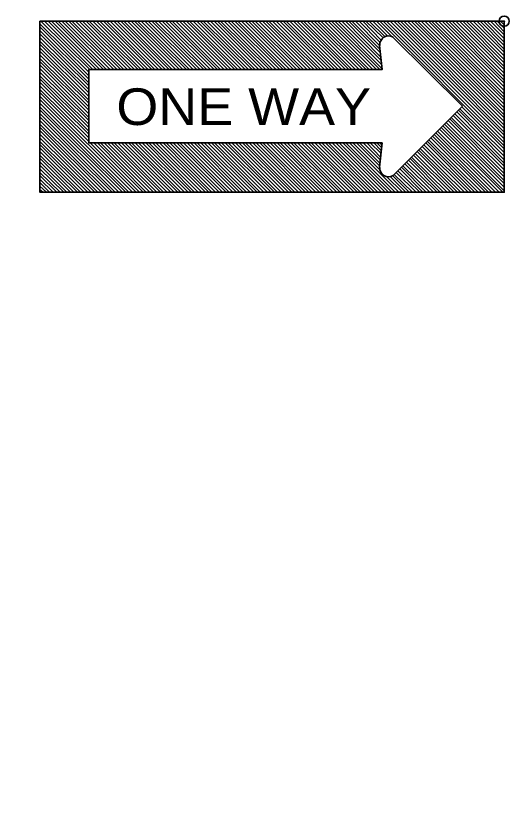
# Model space of a CAD drawing. Extents: x -198 to 658, y -402 to 142.
# Drawn here: x 499.68 to 522.95, y -202.97 to -165.99 of the extents above; entities that cross this region are included whole.
import ezdxf
from ezdxf.enums import TextEntityAlignment as Align

# ---------------------------------------------------------------- set-up
doc = ezdxf.new("R2010")
doc.units = 0
doc.header["$LTSCALE"] = 0.96
doc.header["$PDMODE"] = 32
doc.header["$PDSIZE"] = 0.48
doc.layers.add('1', color=7, linetype='Continuous', lineweight=35)

msp = doc.modelspace()

# ---------------------------------------------------------------- linework, layer by layer
at = {"layer": '1'}
for p, q in [((503.1263, -168.6473), (500.8223, -166.3673)), ((503.1743, -168.5273), (500.8703, -166.2473)), ((503.3183, -168.5273), (501.0383, -166.2473)), ((503.4863, -168.5273), (501.2063, -166.2473)), ((503.6543, -168.5273), (501.3743, -166.2473)), ((503.8223, -168.5273), (501.5423, -166.2473)), ((503.9663, -168.5273), (501.6863, -166.2473)), ((504.1343, -168.5273), (501.8543, -166.2473)), ((504.3023, -168.5273), (502.0223, -166.2473)), ((504.4703, -168.5273), (502.1903, -166.2473)), ((504.6383, -168.5273), (502.3343, -166.2473)), ((504.7823, -168.5273), (502.5023, -166.2473)), ((504.9503, -168.5273), (502.6703, -166.2473)), ((505.1183, -168.5273), (502.8383, -166.2473)), ((505.2863, -168.5273), (503.0063, -166.2473)), ((505.4543, -168.5273), (503.1503, -166.2473)), ((505.5983, -168.5273), (503.3183, -166.2473)), ((505.7663, -168.5273), (503.4863, -166.2473)), ((505.9343, -168.5273), (503.6543, -166.2473)), ((506.1023, -168.5273), (503.8223, -166.2473)), ((506.2463, -168.5273), (503.9663, -166.2473)), ((506.4143, -168.5273), (504.1343, -166.2473)), ((506.5823, -168.5273), (504.3023, -166.2473)), ((506.7503, -168.5273), (504.4703, -166.2473)), ((506.9183, -168.5273), (504.6383, -166.2473)), ((507.0623, -168.5273), (504.7823, -166.2473)), ((507.2303, -168.5273), (504.9503, -166.2473)), ((507.3983, -168.5273), (505.1183, -166.2473)), ((507.5663, -168.5273), (505.2863, -166.2473)), ((507.7343, -168.5273), (505.4303, -166.2473)), ((507.8783, -168.5273), (505.5983, -166.2473)), ((508.0463, -168.5273), (505.7663, -166.2473)), ((508.2143, -168.5273), (505.9343, -166.2473)), ((508.3823, -168.5273), (506.1023, -166.2473)), ((508.5503, -168.5273), (506.2463, -166.2473)), ((508.6943, -168.5273), (506.4143, -166.2473)), ((508.8623, -168.5273), (506.5823, -166.2473)), ((509.0303, -168.5273), (506.7503, -166.2473)), ((509.1983, -168.5273), (506.9183, -166.2473)), ((509.3423, -168.5273), (507.0623, -166.2473)), ((509.5103, -168.5273), (507.2303, -166.2473)), ((509.6783, -168.5273), (507.3983, -166.2473)), ((509.8463, -168.5273), (507.5663, -166.2473)), ((510.0143, -168.5273), (507.7343, -166.2473)), ((510.1583, -168.5273), (507.8783, -166.2473)), ((510.3263, -168.5273), (508.0463, -166.2473)), ((510.4943, -168.5273), (508.2143, -166.2473)), ((510.6623, -168.5273), (508.3823, -166.2473)), ((510.8303, -168.5273), (508.5263, -166.2473)), ((510.9743, -168.5273), (508.6943, -166.2473)), ((511.1423, -168.5273), (508.8623, -166.2473)), ((511.3103, -168.5273), (509.0303, -166.2473)), ((511.4783, -168.5273), (509.1983, -166.2473)), ((511.6463, -168.5273), (509.3423, -166.2473)), ((511.7903, -168.5273), (509.5103, -166.2473)), ((511.9583, -168.5273), (509.6783, -166.2473)), ((512.1263, -168.5273), (509.8463, -166.2473)), ((512.2943, -168.5273), (510.0143, -166.2473)), ((512.4383, -168.5273), (510.1583, -166.2473)), ((512.6063, -168.5273), (510.3263, -166.2473)), ((512.7743, -168.5273), (510.4943, -166.2473)), ((512.9423, -168.5273), (510.6623, -166.2473)), ((513.1103, -168.5273), (510.8063, -166.2473)), ((513.2543, -168.5273), (510.9743, -166.2473)), ((513.4223, -168.5273), (511.1423, -166.2473)), ((513.5903, -168.5273), (511.3103, -166.2473)), ((513.7583, -168.5273), (511.4783, -166.2473)), ((513.9263, -168.5273), (511.6223, -166.2473)), ((514.0703, -168.5273), (511.7903, -166.2473)), ((514.2383, -168.5273), (511.9583, -166.2473)), ((514.4063, -168.5273), (512.1263, -166.2473)), ((514.5743, -168.5273), (512.2943, -166.2473)), ((514.7183, -168.5273), (512.4383, -166.2473)), ((514.8863, -168.5273), (512.6063, -166.2473)), ((515.0543, -168.5273), (512.7743, -166.2473)), ((515.2223, -168.5273), (512.9423, -166.2473)), ((515.3903, -168.5273), (513.1103, -166.2473)), ((515.5343, -168.5273), (513.2543, -166.2473)), ((515.7023, -168.5273), (513.4223, -166.2473)), ((515.8703, -168.5273), (513.5903, -166.2473)), ((516.0383, -168.5273), (513.7583, -166.2473)), ((516.2063, -168.5273), (513.9023, -166.2473)), ((516.3503, -168.5273), (514.0703, -166.2473)), ((516.5183, -168.5273), (514.2383, -166.2473)), ((516.6863, -168.5273), (514.4063, -166.2473)), ((516.8543, -168.5273), (514.5743, -166.2473)), ((516.9263, -168.4553), (514.7183, -166.2473)), ((516.9263, -168.2873), (514.8863, -166.2473)), ((516.9023, -168.0953), (515.0543, -166.2473)), ((516.8783, -167.9273), (515.2223, -166.2473)), ((516.8783, -167.7353), (515.3903, -166.2473)), ((516.8543, -167.5673), (515.5343, -166.2473)), ((516.8303, -167.3993), (515.7023, -166.2473)), ((516.8543, -167.2313), (515.8703, -166.2473)), ((516.9023, -167.1353), (516.0383, -166.2473)), ((516.9983, -167.0393), (516.1823, -166.2473)), ((517.0943, -166.9913), (516.3503, -166.2473)), ((517.2143, -166.9433), (516.5183, -166.2473)), ((517.4063, -166.9673), (516.6863, -166.2473)), ((522.7103, -172.1273), (516.8543, -166.2473)), ((522.7103, -171.9593), (516.9983, -166.2473)), ((522.7103, -171.7913), (517.1663, -166.2473)), ((522.7103, -171.6233), (517.3343, -166.2473)), ((522.7103, -171.4793), (517.5023, -166.2473)), ((522.7103, -171.3113), (517.6703, -166.2473)), ((522.7103, -171.1433), (517.8143, -166.2473)), ((522.7103, -170.9753), (517.9823, -166.2473)), ((522.7103, -170.8073), (518.1503, -166.2473)), ((522.7103, -170.6633), (518.3183, -166.2473)), ((522.7103, -170.4953), (518.4863, -166.2473)), ((522.7103, -170.3273), (518.6303, -166.2473)), ((522.7103, -170.1593), (518.7983, -166.2473)), ((522.7103, -169.9913), (518.9663, -166.2473)), ((522.7103, -169.8473), (519.1343, -166.2473)), ((522.7103, -169.6793), (519.2783, -166.2473)), ((522.7103, -169.5113), (519.4463, -166.2473)), ((522.7103, -169.3433), (519.6143, -166.2473)), ((522.7103, -169.1753), (519.7823, -166.2473)), ((522.7103, -169.0313), (519.9503, -166.2473)), ((522.7103, -168.8633), (520.0943, -166.2473)), ((522.7103, -168.6953), (520.2623, -166.2473)), ((522.7103, -168.5273), (520.4303, -166.2473)), ((522.7103, -168.3833), (520.5983, -166.2473)), ((522.7103, -168.2153), (520.7663, -166.2473)), ((522.7103, -168.0473), (520.9103, -166.2473)), ((522.7103, -167.8793), (521.0783, -166.2473)), ((522.7103, -167.7113), (521.2463, -166.2473)), ((522.7103, -167.5673), (521.4143, -166.2473)), ((522.7103, -167.3993), (521.5823, -166.2473)), ((522.7103, -167.2313), (521.7263, -166.2473)), ((522.7103, -167.0633), (521.8943, -166.2473)), ((522.7103, -166.8953), (522.0623, -166.2473)), ((522.7103, -166.7513), (522.2303, -166.2473)), ((522.7103, -166.5833), (522.3743, -166.2473)), ((522.7103, -166.4153), (522.5423, -166.2473)), ((503.1263, -168.8153), (500.8223, -166.5113)), ((503.1263, -168.9833), (500.8223, -166.6793)), ((503.1263, -169.1513), (500.8223, -166.8473)), ((503.1263, -169.2953), (500.8223, -167.0153)), ((520.7423, -170.2553), (517.4783, -167.0153)), ((503.1263, -169.4633), (500.8223, -167.1833)), ((503.1263, -169.6313), (500.8223, -167.3273)), ((503.1263, -169.7993), (500.8223, -167.4953)), ((503.1263, -169.9673), (500.8223, -167.6633)), ((503.1263, -170.1113), (500.8223, -167.8313)), ((503.1263, -170.2793), (500.8223, -167.9993)), ((503.1263, -170.4473), (500.8223, -168.1433)), ((503.1263, -170.6153), (500.8223, -168.3113)), ((503.1263, -170.7833), (500.8223, -168.4793)), ((503.1263, -170.9273), (500.8223, -168.6473)), ((503.1263, -171.0953), (500.8223, -168.8153)), ((503.1263, -171.2633), (500.8223, -168.9593)), ((503.1263, -171.4313), (500.8223, -169.1273)), ((503.1263, -171.5753), (500.8223, -169.2953)), ((503.1263, -171.7433), (500.8223, -169.4633)), ((503.1263, -171.9113), (500.8223, -169.6073)), ((505.3583, -174.3113), (500.8223, -169.7753)), ((505.1903, -174.3113), (500.8223, -169.9433)), ((505.0223, -174.3113), (500.8223, -170.1113)), ((504.8783, -174.3113), (500.8223, -170.2793)), ((504.7103, -174.3113), (500.8223, -170.4233)), ((517.4783, -173.5193), (520.7423, -170.2553)), ((522.7103, -172.6073), (520.5503, -170.4473)), ((522.7103, -172.4393), (520.6223, -170.3753)), ((522.7103, -172.2713), (520.7183, -170.2793)), ((504.5423, -174.3113), (500.8223, -170.5913)), ((504.3743, -174.3113), (500.8223, -170.7593)), ((522.7103, -173.4233), (520.1423, -170.8553)), ((522.7103, -173.2553), (520.2143, -170.7833)), ((522.7103, -173.0873), (520.3103, -170.6873)), ((522.7103, -172.9433), (520.3823, -170.6153)), ((522.7103, -172.7753), (520.4783, -170.5193)), ((504.2303, -174.3113), (500.8223, -170.9273)), ((504.0623, -174.3113), (500.8223, -171.0953)), ((503.8943, -174.3113), (500.8223, -171.2393)), ((522.7103, -174.0713), (519.8303, -171.1913)), ((522.7103, -173.9033), (519.9023, -171.0953)), ((522.7103, -173.7593), (519.9743, -171.0233)), ((522.7103, -173.5913), (520.0703, -170.9273)), ((503.7263, -174.3113), (500.8223, -171.4073)), ((503.5583, -174.3113), (500.8223, -171.5753)), ((522.1343, -174.3113), (519.4223, -171.5993)), ((522.3023, -174.3113), (519.4943, -171.5033)), ((522.4703, -174.3113), (519.5663, -171.4313)), ((522.6383, -174.3113), (519.6623, -171.3353)), ((522.7103, -174.2393), (519.7343, -171.2633)), ((503.4143, -174.3113), (500.8223, -171.7433)), ((503.2463, -174.3113), (500.8223, -171.9113)), ((505.5263, -174.3113), (503.1983, -171.9833)), ((505.6943, -174.3113), (503.3663, -171.9833)), ((505.8383, -174.3113), (503.5343, -171.9833)), ((506.0063, -174.3113), (503.6783, -171.9833)), ((506.1743, -174.3113), (503.8463, -171.9833)), ((506.3423, -174.3113), (504.0143, -171.9833)), ((506.5103, -174.3113), (504.1823, -171.9833)), ((506.6543, -174.3113), (504.3263, -171.9833)), ((506.8223, -174.3113), (504.4943, -171.9833)), ((506.9903, -174.3113), (504.6623, -171.9833)), ((507.1583, -174.3113), (504.8303, -171.9833)), ((507.3263, -174.3113), (504.9983, -171.9833)), ((507.4703, -174.3113), (505.1423, -171.9833)), ((507.6383, -174.3113), (505.3103, -171.9833)), ((507.8063, -174.3113), (505.4783, -171.9833)), ((507.9743, -174.3113), (505.6463, -171.9833)), ((508.1183, -174.3113), (505.8143, -171.9833)), ((508.2863, -174.3113), (505.9583, -171.9833)), ((508.4543, -174.3113), (506.1263, -171.9833)), ((508.6223, -174.3113), (506.2943, -171.9833)), ((508.7903, -174.3113), (506.4623, -171.9833)), ((508.9343, -174.3113), (506.6303, -171.9833)), ((509.1023, -174.3113), (506.7743, -171.9833)), ((509.2703, -174.3113), (506.9423, -171.9833)), ((509.4383, -174.3113), (507.1103, -171.9833)), ((509.6063, -174.3113), (507.2783, -171.9833)), ((509.7503, -174.3113), (507.4223, -171.9833)), ((509.9183, -174.3113), (507.5903, -171.9833)), ((510.0863, -174.3113), (507.7583, -171.9833)), ((510.2543, -174.3113), (507.9263, -171.9833)), ((510.3983, -174.3113), (508.0943, -171.9833)), ((510.5663, -174.3113), (508.2383, -171.9833)), ((510.7343, -174.3113), (508.4063, -171.9833)), ((510.9023, -174.3113), (508.5743, -171.9833)), ((511.0703, -174.3113), (508.7423, -171.9833)), ((511.2143, -174.3113), (508.9103, -171.9833)), ((511.3823, -174.3113), (509.0543, -171.9833)), ((511.5503, -174.3113), (509.2223, -171.9833)), ((511.7183, -174.3113), (509.3903, -171.9833)), ((511.8863, -174.3113), (509.5583, -171.9833)), ((512.0303, -174.3113), (509.7023, -171.9833)), ((512.1983, -174.3113), (509.8703, -171.9833)), ((512.3663, -174.3113), (510.0383, -171.9833)), ((512.5343, -174.3113), (510.2063, -171.9833)), ((512.7023, -174.3113), (510.3743, -171.9833)), ((512.8463, -174.3113), (510.5183, -171.9833)), ((513.0143, -174.3113), (510.6863, -171.9833)), ((513.1823, -174.3113), (510.8543, -171.9833)), ((513.3503, -174.3113), (511.0223, -171.9833)), ((513.4943, -174.3113), (511.1903, -171.9833)), ((513.6623, -174.3113), (511.3343, -171.9833)), ((513.8303, -174.3113), (511.5023, -171.9833)), ((513.9983, -174.3113), (511.6703, -171.9833)), ((514.1663, -174.3113), (511.8383, -171.9833)), ((514.3103, -174.3113), (512.0063, -171.9833)), ((514.4783, -174.3113), (512.1503, -171.9833)), ((514.6463, -174.3113), (512.3183, -171.9833)), ((514.8143, -174.3113), (512.4863, -171.9833)), ((514.9823, -174.3113), (512.6543, -171.9833)), ((515.1263, -174.3113), (512.7983, -171.9833)), ((515.2943, -174.3113), (512.9663, -171.9833)), ((515.4623, -174.3113), (513.1343, -171.9833)), ((515.6303, -174.3113), (513.3023, -171.9833)), ((515.7983, -174.3113), (513.4703, -171.9833)), ((515.9423, -174.3113), (513.6143, -171.9833)), ((516.1103, -174.3113), (513.7823, -171.9833)), ((516.2783, -174.3113), (513.9503, -171.9833)), ((516.4463, -174.3113), (514.1183, -171.9833)), ((516.5903, -174.3113), (514.2863, -171.9833)), ((516.7583, -174.3113), (514.4303, -171.9833)), ((516.9263, -174.3113), (514.5983, -171.9833)), ((517.0943, -174.3113), (514.7663, -171.9833)), ((517.2623, -174.3113), (514.9343, -171.9833)), ((517.4063, -174.3113), (515.1023, -171.9833)), ((517.5743, -174.3113), (515.2463, -171.9833)), ((517.7423, -174.3113), (515.4143, -171.9833)), ((516.8543, -173.2553), (515.5823, -171.9833)), ((516.8543, -173.0873), (515.7503, -171.9833)), ((516.8543, -172.9433), (515.8943, -171.9833)), ((516.8783, -172.7993), (516.0623, -171.9833)), ((516.8783, -172.6553), (516.2303, -171.9833)), ((516.9023, -172.4873), (516.3983, -171.9833)), ((516.9023, -172.3433), (516.5663, -171.9833)), ((516.9263, -172.1993), (516.7103, -171.9833)), ((516.9263, -172.0553), (516.8783, -171.9833)), ((521.3183, -174.3113), (519.0143, -171.9833)), ((521.4863, -174.3113), (519.0863, -171.9113)), ((521.6543, -174.3113), (519.1583, -171.8393)), ((521.8223, -174.3113), (519.2543, -171.7433)), ((521.9663, -174.3113), (519.3263, -171.6713)), ((503.0783, -174.3113), (500.8223, -172.0553)), ((502.9103, -174.3113), (500.8223, -172.2233)), ((520.6703, -174.3113), (518.6783, -172.3193)), ((520.8383, -174.3113), (518.7503, -172.2473)), ((521.0063, -174.3113), (518.8463, -172.1513)), ((521.1743, -174.3113), (518.9183, -172.0793)), ((502.7423, -174.3113), (500.8223, -172.3913)), ((502.5983, -174.3113), (500.8223, -172.5593)), ((502.4303, -174.3113), (500.8223, -172.7033)), ((520.0223, -174.3113), (518.3423, -172.6553)), ((520.1903, -174.3113), (518.4383, -172.5593)), ((520.3583, -174.3113), (518.5103, -172.4873)), ((520.5023, -174.3113), (518.6063, -172.3913)), ((502.2623, -174.3113), (500.8223, -172.8713)), ((502.0943, -174.3113), (500.8223, -173.0393)), ((519.2063, -174.3113), (517.9343, -173.0633)), ((519.3743, -174.3113), (518.0303, -172.9673)), ((519.5423, -174.3113), (518.1023, -172.8953)), ((519.6863, -174.3113), (518.1983, -172.7993)), ((519.8543, -174.3113), (518.2703, -172.7273)), ((501.9503, -174.3113), (500.8223, -173.2073)), ((501.7823, -174.3113), (500.8223, -173.3753)), ((518.5583, -174.3113), (517.6223, -173.3753)), ((518.7263, -174.3113), (517.6943, -173.3033)), ((518.8703, -174.3113), (517.7903, -173.2073)), ((519.0383, -174.3113), (517.8623, -173.1353)), ((501.6143, -174.3113), (500.8223, -173.5193)), ((501.4463, -174.3113), (500.8223, -173.6873)), ((517.9103, -174.3113), (517.1663, -173.5673)), ((518.0783, -174.3113), (517.3343, -173.5673)), ((518.2223, -174.3113), (517.4543, -173.5433)), ((518.3903, -174.3113), (517.5263, -173.4713)), ((501.2783, -174.3113), (500.8223, -173.8553)), ((501.1343, -174.3113), (500.8223, -174.0233)), ((500.9663, -174.3113), (500.8223, -174.1913))]:
    msp.add_line(p, q, dxfattribs=at)
msp.add_lwpolyline([(522.7103, -166.2473), (500.8223, -166.2473), (500.8223, -174.3113), (522.7103, -174.3113)], close=True, dxfattribs=at)
msp.add_lwpolyline([(516.8303, -167.3993), (516.9503, -168.5273), (503.1263, -168.5273), (503.1263, -171.9833), (516.9503, -171.9833), (516.8303, -173.1353)], dxfattribs=at)
at = {"layer": '1', "lineweight": 53}
msp.add_arc((507.3947, -202.974), 60, 90, 180, dxfattribs=at)
at = {"layer": '1'}
for centre, start, end in [((517.2595, -167.3637), 58.76645, 183.36449), ((517.2595, -173.164), 176.63551, 301.23355)]:
    msp.add_arc(centre, 0.419, start, end, dxfattribs=at)
msp.add_point((522.7103, -166.2473), dxfattribs=at)

# ---------------------------------------------------------------- texts
at = {"layer": '1', "width": 1.1}
msp.add_text('ONE WAY', height=1.728, dxfattribs=at).set_placement((510.4291, -171.1412), align=Align.CENTER)

doc.saveas('drawing.dxf')
